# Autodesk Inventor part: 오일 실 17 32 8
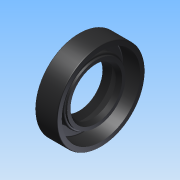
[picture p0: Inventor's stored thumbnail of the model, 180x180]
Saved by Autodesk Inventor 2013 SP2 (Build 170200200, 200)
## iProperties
Created: 2026-07
Part Number: 오일 실 17 32 8
Material: Generic
Document SubType Name: Modeling
Designer: 601
Density: 1 g/cm^3
Author: 601
변환 표준: STEP AP214IS
전처리기: Build: 200, Release: 2013 SP2 Update 6 - Date: Thu 07/17/2014
전송 단위: 밀리미터
불확실성: 0.01
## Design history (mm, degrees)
node "오일 실 17 32 81"
body "Solid1"
node "기준1"
